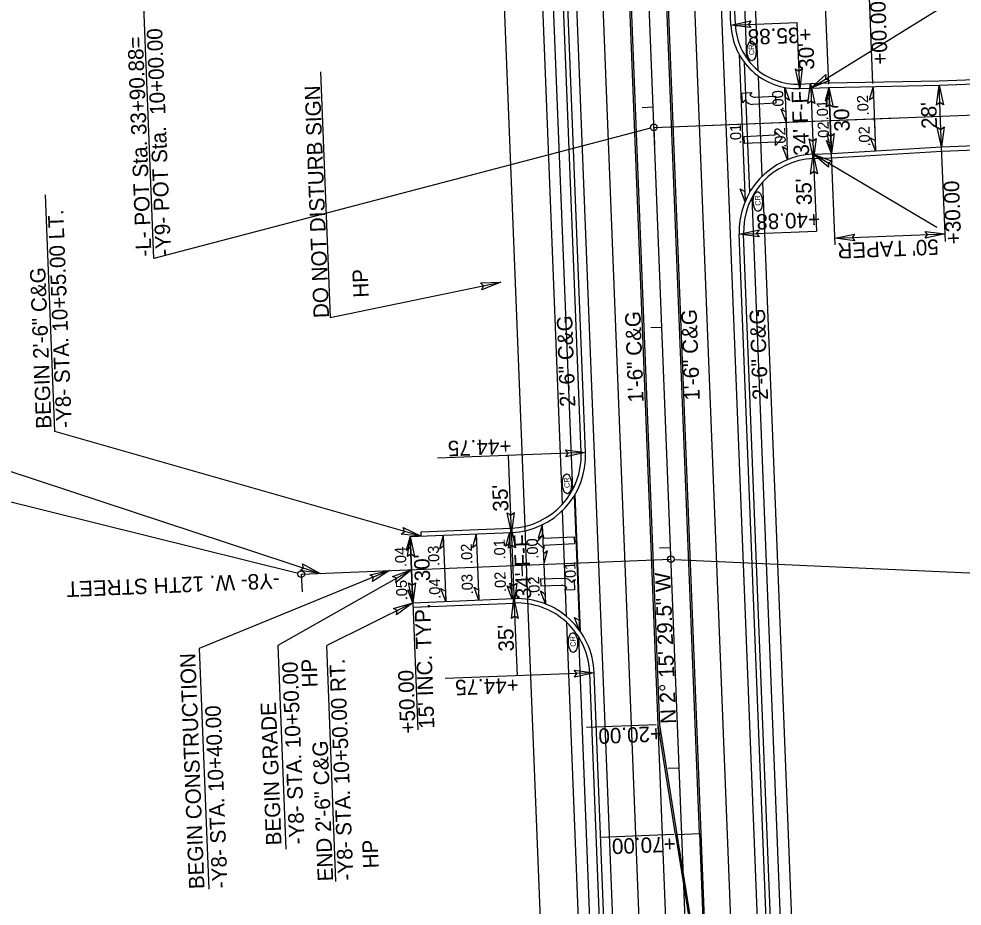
# Model space of a CAD drawing. Extents: x 1627861 to 1629601, y 761281 to 766239.
# Drawn here: x 1628128.8 to 1628556.5, y 763511.7 to 763914.2 of the extents above; entities that cross this region are included whole.
import ezdxf

# ---------------------------------------------------------------- set-up
doc = ezdxf.new("R2010")
doc.units = 0
for name, color, linetype in [('Cogo Default Point CELL', 7, 'Continuous'), ('Exist Other Culture Sign Leader', 7, 'Continuous'), ('Exist Property Tie Line Text', 7, 'Continuous'), ('Exist Right of Way Line Leader', 7, 'Continuous'), ('Exist Right of Way Monument Leader', 7, 'Continuous'), ('Exist Right of Way Monument Text', 7, 'Continuous'), ('Exist Utilities Gas Meter CELL', 7, 'Continuous'), ('Exist Utilities Gas Meter Cogo Elevation', 7, 'Continuous'), ('Exist Utilities Gas Meter Cogo Number', 7, 'Continuous'), ('Exist Utilities Gas UG Line', 7, 'Continuous'), ('Exist Utilities Other Unknown UG SUE Text', 7, 'Continuous'), ('Exist Utilities Power UG Cable SUE LOS B Cogo Point CELL', 7, 'Continuous'), ('Exist Utilities Telephone UG Cable SUE LOS B Cogo Comment', 7, 'Continuous'), ('Exist Utilities Telephone UG Cable SUE LOS B Cogo Point CELL', 7, 'Continuous'), ('Exist Utilities Water Fire Hydrant Cogo Elevation', 7, 'Continuous'), ('Exist Utilities Water Fire Hydrant Cogo Number', 7, 'Continuous'), ('Exist Utilities Water Meter Cogo Elevation', 7, 'Continuous'), ('Exist Utilities Water UG Line SUE LOS B Cogo Number', 7, 'Continuous'), ('Exist Utilities Water Valve CELL', 7, 'Continuous'), ('Matchline', 7, 'Continuous'), ('Scratch_Level_0', 7, 'Continuous'), ('Typical Terminator CELL', 7, 'Continuous')]:
    doc.layers.add(name, color=color, linetype=linetype)

msp = doc.modelspace()

# ---------------------------------------------------------------- linework, layer by layer
at = {"layer": 'Exist Property Tie Line Text'}
for p, q in [((1628416.35, 763874.07), (1628411.35, 763873.87)), ((1628516.63, 763868.89), (1628516.83, 763863.9)), ((1628420.29, 763774.14), (1628415.29, 763773.95)), ((1628424.23, 763674.22), (1628419.23, 763674.02)), ((1628356.81, 763666.31), (1628357.01, 763661.32)), ((1628428.17, 763574.3), (1628423.17, 763574.1))]:
    msp.add_line(p, q, dxfattribs=at)
at = {"layer": 'Exist Right of Way Line Leader'}
for p, q in [((1628190.01, 763805.52), (1628185.22, 763927.11)), ((1628415.25, 763864.6), (1628190.01, 763805.52)), ((1628123.89, 763709.23), (1628265.43, 763662.63)), ((1628255.44, 763662.64), (1628111.59, 763698.24)), ((1628425.93, 763668.97), (1628567.57, 763662.49))]:
    msp.add_line(p, q, dxfattribs=at)
for centre in [(1628416.71, 763864.95), (1628416.71, 763864.95), (1628424.43, 763669.04), (1628256.89, 763662.28)]:
    msp.add_circle(centre, 1.5, dxfattribs=at)
at = {"layer": 'Exist Right of Way Monument Leader'}
for p, q in [((1628456.66, 763880.51), (1628461.15, 763880.8)), ((1628456.94, 763876.12), (1628456.66, 763880.51)), ((1628457.94, 763877.23), (1628456.94, 763876.12)), ((1628461.15, 763880.8), (1628460.16, 763879.7)), ((1628462.72, 763878.68), (1628471.85, 763879.17)), ((1628471.85, 763879.17), (1628472.03, 763875.88)), ((1628472.03, 763875.88), (1628461.49, 763875.31)), ((1628457.67, 763860.85), (1628471.66, 763861.51)), ((1628457.83, 763857.55), (1628457.67, 763860.85)), ((1628471.66, 763861.51), (1628471.59, 763863)), ((1628471.59, 763863), (1628474.88, 763860.06)), ((1628471.81, 763858.21), (1628457.83, 763857.55)), ((1628471.88, 763856.71), (1628471.81, 763858.21)), ((1628474.88, 763860.06), (1628471.88, 763856.71)), ((1628363.59, 763676.75), (1628366.59, 763680.09)), ((1628366.88, 763673.8), (1628363.59, 763676.75)), ((1628366.59, 763680.09), (1628366.66, 763678.59)), ((1628366.66, 763678.59), (1628380.64, 763679.25)), ((1628380.64, 763679.25), (1628380.8, 763675.95)), ((1628380.8, 763675.95), (1628366.81, 763675.3)), ((1628366.81, 763675.3), (1628366.88, 763673.8)), ((1628365.47, 763660.14), (1628376.01, 763660.51)), ((1628365.59, 763656.84), (1628365.47, 763660.14)), ((1628379.54, 763658.54), (1628380.55, 763659.63)), ((1628380.55, 763659.63), (1628380.76, 763655.23)), ((1628374.73, 763657.17), (1628365.59, 763656.84)), ((1628376.26, 763655.02), (1628377.27, 763656.11)), ((1628380.76, 763655.23), (1628376.26, 763655.02))]:
    msp.add_line(p, q, dxfattribs=at)
for centre, radius, start, end in [((1628462.01, 763880.52), 5.25, 219.0734, 264.3851), ((1628462.53, 763881.94), 3.28, 223.403, 273.0612), ((1628375.41, 763655.31), 5.25, 38.0708, 83.3825), ((1628374.86, 763653.91), 3.28, 42.4004, 92.0586)]:
    msp.add_arc(centre, radius, start, end, dxfattribs=at)
at = {"layer": 'Exist Right of Way Monument Text'}
for p, q in [((1628451.66, 763911.37), (1628428.17, 764506.9)), ((1628418.64, 763593.94), (1628385.15, 764443.28)), ((1628438.1, 763544.67), (1628404.6, 764394.05)), ((1628385.75, 763717.49), (1628371.05, 764090.05)), ((1628482.82, 763882.57), (1628487.81, 763882.77)), ((1628487.81, 763882.77), (1628496.06, 763883.09)), ((1628496.06, 763883.09), (1628546.06, 763884.07)), ((1628546.06, 763884.07), (1628566.04, 763884.85)), ((1628497.24, 763853.12), (1628547.16, 763856.09)), ((1628547.16, 763856.09), (1628567.14, 763856.88)), ((1628488.99, 763852.79), (1628497.24, 763853.12)), ((1628476.63, 763278.07), (1628455.4, 763816.44)), ((1628306.25, 763679.29), (1628352.18, 763681.14)), ((1628351.09, 763681.09), (1628351.18, 763681.1)), ((1628307.46, 763649.31), (1628353.3, 763651.16)), ((1628404.27, 763247.66), (1628389.69, 763617.57)), ((1628426.6, 763544.21), (1628418.63, 763593.98))]:
    msp.add_line(p, q, dxfattribs=at)
for centre, radius, start, end in [((1628481.63, 763912.55), 30, 182.2582, 272.2589), ((1628490.37, 763817.82), 35, 92.2589, 182.2582), ((1628350.77, 763716.11), 35, 272.3088, 2.2582), ((1628354.71, 763616.19), 35, 2.2582, 92.3088)]:
    msp.add_arc(centre, radius, start, end, dxfattribs=at)
at = {"layer": 'Exist Utilities Gas Meter CELL'}
for p, q in [((1628486.22, 762102.11), (1628373.12, 764970.45)), ((1628416.71, 763864.95), (1628726.66, 763877.18)), ((1628416.71, 763864.95), (1628726.66, 763877.18)), ((1628416.71, 763864.95), (1628526.81, 763869.3)), ((1628256.89, 763662.28), (1628424.43, 763669.04)), ((1628256.89, 763662.28), (1628424.43, 763669.04))]:
    msp.add_line(p, q, dxfattribs=at)
at = {"layer": 'Exist Utilities Gas Meter Cogo Elevation'}
for p, q in [((1628453.66, 763911.45), (1628430.17, 764506.97)), ((1628383.75, 763717.41), (1628369.06, 764089.97)), ((1628482.74, 763884.57), (1628487.73, 763884.77)), ((1628478.63, 763278.15), (1628457.4, 763816.52)), ((1628311.16, 763681.49), (1628352.1, 763683.14)), ((1628311.24, 763679.49), (1628311.16, 763681.49)), ((1628351.01, 763683.09), (1628351.1, 763683.1)), ((1628307.54, 763647.31), (1628353.38, 763649.16)), ((1628402.27, 763247.58), (1628387.69, 763617.49))]:
    msp.add_line(p, q, dxfattribs=at)
for centre, radius, start, end in [((1628481.63, 763912.55), 28, 182.2582, 272.2589), ((1628490.37, 763817.82), 33, 92.2589, 182.2582), ((1628350.77, 763716.11), 33, 272.3088, 2.2582), ((1628354.71, 763616.19), 33, 2.2582, 92.3088)]:
    msp.add_arc(centre, radius, start, end, dxfattribs=at)
at = {"layer": 'Exist Utilities Gas Meter Cogo Number'}
for points in [[(1628460.71, 763910.17), (1628451.66, 763911.37), (1628460.64, 763913.32), (1628459.55, 763911.68)], [(1628484.01, 763891.63), (1628482.82, 763882.57), (1628480.86, 763891.55), (1628482.5, 763890.47)], [(1628496.28, 763886.19), (1628487.81, 763882.77), (1628494.67, 763888.89), (1628494.53, 763886.93)], [(1628486.54, 763875.71), (1628487.73, 763884.77), (1628489.69, 763875.79), (1628488.04, 763876.87)], [(1628494.86, 763874.04), (1628496.06, 763883.09), (1628498.01, 763874.11), (1628496.37, 763875.2)], [(1628544.86, 763875.01), (1628546.06, 763884.07), (1628548.01, 763875.09), (1628546.37, 763876.17)], [(1628548.35, 763865.14), (1628547.16, 763856.09), (1628545.2, 763865.07), (1628546.85, 763863.98)], [(1628498.43, 763862.17), (1628497.24, 763853.12), (1628495.28, 763862.1), (1628496.93, 763861.01)], [(1628490.27, 763859.85), (1628489.07, 763850.79), (1628487.12, 763859.77), (1628488.76, 763858.69)], [(1628487.8, 763843.74), (1628488.99, 763852.79), (1628490.95, 763843.81), (1628489.3, 763844.9)], [(1628495.94, 763846.87), (1628488.99, 763852.79), (1628497.59, 763849.55), (1628495.79, 763848.76)], [(1628464.45, 763815.25), (1628455.4, 763816.44), (1628464.38, 763818.4), (1628463.29, 763816.75)], [(1628539.66, 763817.77), (1628548.72, 763816.58), (1628539.74, 763814.62), (1628540.82, 763816.27)], [(1628507.81, 763813.42), (1628498.76, 763814.61), (1628507.74, 763816.57), (1628506.65, 763814.92)], [(1628338.15, 763794.35), (1628347.28, 763794.65), (1628338.74, 763791.26), (1628339.54, 763793.06)], [(1628376.69, 763718.68), (1628385.75, 763717.49), (1628376.77, 763715.53), (1628377.85, 763717.18)], [(1628353.37, 763690.19), (1628352.18, 763681.14), (1628350.22, 763690.12), (1628351.86, 763689.03)], [(1628303.02, 763683.45), (1628311.24, 763679.49), (1628302.1, 763680.44), (1628303.65, 763681.66)], [(1628350.83, 763674.08), (1628352.01, 763683.13), (1628353.98, 763674.15), (1628352.33, 763675.24)], [(1628305.06, 763670.23), (1628306.25, 763679.29), (1628308.21, 763670.31), (1628306.57, 763671.39)], [(1628257.37, 763666.91), (1628265.43, 763662.63), (1628256.34, 763663.94), (1628257.93, 763665.1)], [(1628287.95, 763661.91), (1628296.86, 763663.9), (1628289.1, 763658.98), (1628289.55, 763660.9)], [(1628298.26, 763661.2), (1628306.85, 763664.3), (1628299.77, 763658.44), (1628299.98, 763660.4)], [(1628308.64, 763658.37), (1628307.46, 763649.31), (1628305.49, 763658.29), (1628307.14, 763657.2)], [(1628354.57, 763658.22), (1628353.38, 763649.16), (1628351.42, 763658.14), (1628353.06, 763657.05)], [(1628352.12, 763642.1), (1628353.3, 763651.16), (1628355.27, 763642.18), (1628353.62, 763643.26)], [(1628298.71, 763646.69), (1628307.46, 763649.31), (1628300.07, 763643.85), (1628300.38, 763645.79)], [(1628380.63, 763618.76), (1628389.69, 763617.57), (1628380.71, 763615.61), (1628381.79, 763617.25)]]:
    msp.add_lwpolyline(points, close=True, dxfattribs=at)
at = {"layer": 'Exist Utilities Gas UG Line'}
for p, q in [((1628420.44, 763243.74), (1628359.36, 764792.53)), ((1628462.18, 763238.38), (1628400.83, 764794.17)), ((1628474.17, 763238.85), (1628412.82, 764794.64)), ((1628408.48, 763242.45), (1628347.37, 764792.06)), ((1628422.58, 763494.02), (1628418.64, 763593.94)), ((1628426.6, 763544.21), (1628434.57, 763494.49)), ((1628449.84, 763246.9), (1628438.1, 763544.67))]:
    msp.add_line(p, q, dxfattribs=at)
at = {"layer": 'Exist Utilities Other Unknown UG SUE Text'}
for p, q in [((1628427.35, 763544.24), (1628437.35, 763544.64)), ((1628435.32, 763494.52), (1628427.35, 763544.24)), ((1628437.35, 763544.64), (1628449.09, 763246.87))]:
    msp.add_line(p, q, dxfattribs=at)
at = {"layer": 'Exist Utilities Telephone UG Cable SUE LOS B Cogo Comment'}
for p, q in [((1628460.15, 763835.48), (1628457.83, 763894.28)), ((1628465.87, 763842.81), (1628464.08, 763888.22)), ((1628383.45, 763636.17), (1628380.99, 763698.45)), ((1628377.17, 763643.03), (1628375.28, 763691.12))]:
    msp.add_line(p, q, dxfattribs=at)
at = {"layer": 'Exist Utilities Telephone UG Cable SUE LOS B Cogo Point CELL'}
for p, q in [((1628496.02, 763885.09), (1628546.02, 763886.07)), ((1628545.98, 763886.06), (1628565.96, 763886.85)), ((1628487.73, 763884.77), (1628495.98, 763885.09)), ((1628497.36, 763851.12), (1628547.28, 763854.09)), ((1628547.24, 763854.09), (1628567.22, 763854.88)), ((1628489.07, 763850.79), (1628497.32, 763851.12))]:
    msp.add_line(p, q, dxfattribs=at)
at = {"layer": 'Exist Utilities Water Fire Hydrant Cogo Elevation'}
for centre in [(1628461.01, 763899.61), (1628463.85, 763831.26), (1628377.31, 763703.25), (1628380.06, 763631.23)]:
    msp.add_ellipse(centre, major_axis=(-0.18, 4.48), ratio=0.462467, dxfattribs=at)
at = {"layer": 'Exist Utilities Water Fire Hydrant Cogo Number'}
for p, q in [((1628358.23, 763687.61), (1628341.38, 764111.82)), ((1628359.91, 763642.43), (1628358.23, 763687.61)), ((1628376.68, 763217.89), (1628359.91, 763642.43))]:
    msp.add_line(p, q, dxfattribs=at)
at = {"layer": 'Exist Utilities Water Meter Cogo Elevation'}
for p, q in [((1628416.71, 763864.95), (1628417.02, 763856.96)), ((1628256.89, 763662.28), (1628257.22, 763654.29))]:
    msp.add_line(p, q, dxfattribs=at)
at = {"layer": 'Exist Utilities Water UG Line SUE LOS B Cogo Number'}
for p, q in [((1628455.44, 763897.93), (1628458.07, 763831.29)), ((1628476.04, 763883.07), (1628477.33, 763850.3)), ((1628496.06, 763883.04), (1628497.24, 763853.12)), ((1628516.06, 763883.48), (1628517.21, 763854.31)), ((1628380.57, 763697.74), (1628383.02, 763636.76)), ((1628336.22, 763680.49), (1628337.43, 763650.52)), ((1628351.21, 763681.1), (1628352.42, 763651.12)), ((1628366.08, 763684.64), (1628367.53, 763648.76)), ((1628307.46, 763649.31), (1628306.25, 763679.29)), ((1628321.24, 763679.89), (1628322.45, 763649.91))]:
    msp.add_line(p, q, dxfattribs=at)
at = {"layer": 'Exist Utilities Water Valve CELL'}
for p, q in [((1628463.98, 763890.82), (1628438.75, 764530.5)), ((1628434.01, 764523.77), (1628458.75, 763896.41)), ((1628358.65, 764112.75), (1628375.17, 763693.88)), ((1628379.91, 763700.61), (1628363.9, 764106.42)), ((1628465.98, 763840.04), (1628488.12, 763278.53)), ((1628483.12, 763278.33), (1628461.24, 763833.32)), ((1628390.77, 763298.23), (1628377.28, 763640.26)), ((1628382.53, 763633.93), (1628395.77, 763298.19))]:
    msp.add_line(p, q, dxfattribs=at)
at = {"layer": 'Matchline'}
for p, q in [((1628419.39, 763593.97), (1628385.9, 764443.31)), ((1628437.35, 763544.64), (1628403.85, 764393.98)), ((1628427.35, 763544.24), (1628419.39, 763593.97))]:
    msp.add_line(p, q, dxfattribs=at)
at = {"layer": 'Scratch_Level_0'}
for p, q in [((1628487.81, 763882.77), (1628675.94, 763999.17)), ((1628496, 763884.5), (1628494.38, 763925.48)), ((1628516, 763884.77), (1628514.37, 763926.29)), ((1628451.66, 763911.37), (1628481.63, 763912.55)), ((1628482.82, 763882.57), (1628481.63, 763912.55)), ((1628265.6, 763890.15), (1628269.99, 763778.72)), ((1628487.81, 763882.77), (1628489.07, 763850.79)), ((1628497.24, 763853.12), (1628496.06, 763883.09)), ((1628547.16, 763856.09), (1628546.06, 763884.07)), ((1628548.85, 763813.24), (1628547.16, 763856.09)), ((1628488.99, 763852.79), (1628490.37, 763817.82)), ((1628545.07, 763819.53), (1628488.99, 763852.79)), ((1628498.87, 763811.64), (1628497.24, 763853.12)), ((1628145.23, 763726.93), (1628140.99, 763834.35)), ((1628455.4, 763816.44), (1628490.37, 763817.82)), ((1628498.76, 763814.61), (1628548.72, 763816.58)), ((1628269.99, 763778.72), (1628347.28, 763794.65)), ((1628311.24, 763679.49), (1628145.23, 763726.93)), ((1628385.75, 763717.49), (1628318.62, 763714.84)), ((1628352.18, 763681.14), (1628350.77, 763716.11)), ((1628352.01, 763683.13), (1628353.38, 763649.16)), ((1628306.25, 763679.29), (1628307.46, 763649.31)), ((1628296.86, 763663.9), (1628210.62, 763628.51)), ((1628306.85, 763664.3), (1628246.27, 763629.92)), ((1628353.3, 763651.16), (1628354.71, 763616.19)), ((1628307.46, 763649.31), (1628268.39, 763629.87)), ((1628307.46, 763649.31), (1628309.78, 763591.7)), ((1628246.27, 763629.92), (1628249.92, 763537.5)), ((1628272.6, 763522.9), (1628268.39, 763629.87)), ((1628210.62, 763628.51), (1628214.93, 763519.34)), ((1628389.69, 763617.57), (1628322.16, 763614.9)), ((1628417.7, 763593.9), (1628386.23, 763592.66)), ((1628425.81, 763544.18), (1628392.38, 763542.86))]:
    msp.add_line(p, q, dxfattribs=at)
at = {"layer": 'Typical Terminator CELL'}
for points in [[(1628476.04, 763883.07), (1628478.28, 763877.16), (1628476.22, 763878.45)], [(1628496.06, 763883.04), (1628494.3, 763876.97), (1628496.24, 763878.42)], [(1628516.06, 763883.48), (1628514.29, 763877.41), (1628516.24, 763878.86)], [(1628476.66, 763867.32), (1628474.43, 763873.23), (1628476.48, 763871.94)], [(1628517.21, 763854.31), (1628514.97, 763860.22), (1628517.02, 763858.93)], [(1628477.33, 763850.3), (1628475.1, 763856.22), (1628477.15, 763854.92)], [(1628497.24, 763853.12), (1628495, 763859.03), (1628497.06, 763857.74)], [(1628458.07, 763831.22), (1628455.84, 763837.13), (1628457.89, 763835.84)], [(1628336.22, 763680.49), (1628334.47, 763674.42), (1628336.41, 763675.87)], [(1628351.21, 763681.1), (1628349.46, 763675.02), (1628351.4, 763676.48)], [(1628366.08, 763684.64), (1628364.33, 763678.56), (1628366.27, 763680.01)], [(1628306.25, 763679.29), (1628304.49, 763673.21), (1628306.44, 763674.66)], [(1628321.24, 763679.89), (1628319.48, 763673.81), (1628321.42, 763675.27)], [(1628366.8, 763666.71), (1628368.57, 763672.79), (1628366.63, 763671.34)], [(1628307.46, 763649.31), (1628305.22, 763655.22), (1628307.27, 763653.93)], [(1628322.45, 763649.91), (1628320.21, 763655.83), (1628322.26, 763654.54)], [(1628337.43, 763650.52), (1628335.19, 763656.43), (1628337.25, 763655.14)], [(1628352.42, 763651.12), (1628350.18, 763657.04), (1628352.23, 763655.74)], [(1628367.53, 763648.76), (1628365.29, 763654.67), (1628367.34, 763653.38)], [(1628383.02, 763636.76), (1628380.78, 763642.68), (1628382.84, 763641.39)]]:
    msp.add_lwpolyline(points, close=True, dxfattribs=at)

# ---------------------------------------------------------------- texts
at = {"layer": 'Cogo Default Point CELL'}
msp.add_text('N 2%%d 15\' 29.5" W', height=7, rotation=92.2582, dxfattribs=at).set_placement((1628426.86, 763594.51))
at = {"layer": 'Exist Other Culture Sign Leader'}
for s, rotation, p in [('HP', 92.2582, (1628287.48, 763787.84)), ('-Y8- W. 12TH STREET', 182.3088, (1628246.99, 763662.76)), ('BEGIN CONSTRUCTION', 92.2582, (1628213.01, 763519.54)), ('-Y8- STA. 10+50.00', 92.2582, (1628258.43, 763539.8)), ('HP', 92.2582, (1628264.32, 763611.02)), ('BEGIN GRADE', 92.2582, (1628247.94, 763539.38)), ('-Y8- STA. 10+40.00', 92.2582, (1628223.51, 763519.95)), ('HP', 92.2582, (1628291.97, 763528.94))]:
    msp.add_text(s, height=7, rotation=rotation, dxfattribs=at).set_placement(p)
at = {"layer": 'Exist Right of Way Line Leader'}
for s, p in [('-Y9- POT Sta.  10+00.00', (1628197.85, 763806.82)), ('-L- POT Sta. 33+90.88=', (1628188.99, 763806.47))]:
    msp.add_text(s, height=7, rotation=92.2582, dxfattribs=at).set_placement(p)
at = {"layer": 'Exist Utilities Power UG Cable SUE LOS B Cogo Point CELL'}
for s, rotation, p in [('+00.00', 92.0586, (1628522.72, 763893.46)), ('+35.88', 182.2582, (1628488.02, 763910.48)), ("30'", 92.0586, (1628489.52, 763891.19)), ('DO NOT DISTURB SIGN', 92.2582, (1628269.49, 763778.58)), ("34' F-F", 92.0586, (1628487.15, 763852.22)), ("30'", 92.0586, (1628505.56, 763863.19)), ("28'", 92.0586, (1628545.14, 763864.42)), ("35'", 92.0586, (1628488.43, 763829.74)), ('+30.00', 92.0586, (1628556.08, 763812.03)), ('-Y8- STA. 10+55.00 LT.', 92.2582, (1628152.86, 763728.75)), ('+40.88', 182.2582, (1628491.87, 763826.65)), ("50' TAPER", 182.2589, (1628545.73, 763814.2)), ('BEGIN 2\'-6" C&G', 92.2582, (1628143.69, 763728.39)), ('+44.75', 182.2582, (1628352.04, 763723.83)), ("35'", 92.0586, (1628350.83, 763690.79)), ("34' F-F", 92.0586, (1628361.19, 763651.08)), ("30'", 92.0586, (1628315.33, 763659.16)), ("15' INC. TYP.", 92.0586, (1628317.24, 763592.27)), ("35'", 92.0586, (1628353.35, 763627.31)), ('-Y8- STA. 10+50.00 RT.', 92.2582, (1628280.53, 763523.43)), ('+50.00', 92.0586, (1628308.74, 763590.08)), ('+44.75', 182.2582, (1628355.36, 763615.4)), ('END 2\'-6" C&G', 92.2582, (1628271.36, 763523.07))]:
    msp.add_text(s, height=7, rotation=rotation, dxfattribs=at).set_placement(p)
at = {"layer": 'Exist Utilities Water Fire Hydrant Cogo Elevation'}
for p in [(1628462.27, 763897.77), (1628465.1, 763829.43), (1628378.56, 763701.41), (1628381.32, 763629.39)]:
    msp.add_text('CR', height=2.4, rotation=92.2582, dxfattribs=at).set_placement(p)
at = {"layer": 'Exist Utilities Water UG Line SUE LOS B Cogo Number'}
for s, rotation, p in [('.00', 92.2589, (1628475.65, 763872.6)), ('.02', 92.2589, (1628514.11, 763870.44)), ('.01', 92.2589, (1628495.79, 763868.17)), ('.01', 92.2589, (1628456.47, 763857.4)), ('.02', 92.2589, (1628476.64, 763855.77)), ('.02', 92.2589, (1628496.25, 763858.43)), ('.02', 92.2589, (1628514.82, 763856.28)), ('.01', 92.3088, (1628349.46, 763669)), ('.00', 92.3088, (1628364.33, 763669.34)), ('.04', 92.3088, (1628304.56, 763665.49)), ('.03', 92.3088, (1628319.55, 763666.03)), ('.02', 92.3088, (1628334.53, 763666.96)), ('.01', 92.3088, (1628381.46, 763658.75)), ('.05', 92.3088, (1628305.05, 763650.47)), ('.04', 92.3088, (1628320.04, 763651.15)), ('.03', 92.3088, (1628334.78, 763653.17)), ('.02', 92.3088, (1628349.75, 763654.22)), ('.02', 92.3088, (1628365.06, 763652.06))]:
    msp.add_text(s, height=5, rotation=rotation, dxfattribs=at).set_placement(p)
at = {"layer": 'Scratch_Level_0'}
for s, rotation, p in [('2\'-6" C&G', 92.0586, (1628381.15, 763738.26)), ('1\'-6" C&G', 92.0586, (1628412.1, 763740.21)), ('1\'-6" C&G', 92.0586, (1628437.56, 763741.12)), ('2\'-6" C&G', 92.0586, (1628468.51, 763741.39)), ('+20.00', 182.2582, (1628420.3, 763593.38)), ('+70.00', 182.2582, (1628426.44, 763543.37))]:
    msp.add_text(s, height=7, rotation=rotation, dxfattribs=at).set_placement(p)

doc.saveas('drawing.dxf')
